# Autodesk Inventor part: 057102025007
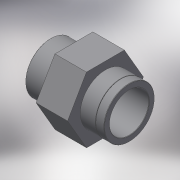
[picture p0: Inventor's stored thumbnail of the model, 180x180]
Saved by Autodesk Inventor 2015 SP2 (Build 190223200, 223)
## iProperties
Created: 2017-10
Part Number: 057102025007
Material: Generic
Description: PLASSON AD. SOCKET REINF.PVC 25-3/4"
Document SubType Name: Modeling
Designer: KIM
Density: 1 g/cm^3
Appearance: Default
Author: KIM
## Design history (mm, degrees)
derived "057102.ipt"
feature "Solid1::057102.ipt"
tag "TaggingFeature1"
body "Solid1"
other parameters: "d1" = 25, "d3" = 24.117, "d4" = 22.5, "d5" = 19, "d6" = 18, "d8" = 28.75, "d10" = 12.6, "d13" = 0, "d14" = 0.25, "d15" = 12, "d16" = 4.5, "d18" = 0.1, "d_" = 25, "G_" = 24.117, "B_" = 12, "l_" = 19, "lt_" = 18
